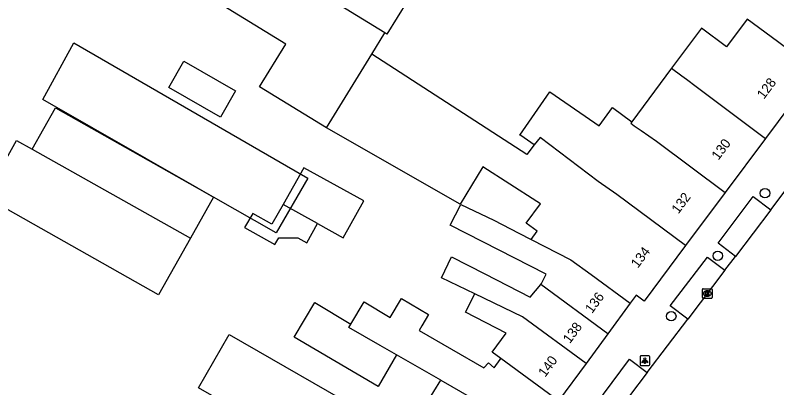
# Model space of a CAD drawing. Extents: x 160107 to 160928, y 382056 to 382918.
# Drawn here: x 160581.9 to 160660.5, y 382406.2 to 382444.7 of the extents above; entities that cross this region are included whole.
import ezdxf

# ---------------------------------------------------------------- set-up
doc = ezdxf.new("R2010")
doc.units = 0
for name, color, linetype in [('IMGEO_Boom', 7, 'Continuous'), ('IMGEO_Kolk', 7, 'Continuous'), ('IMGEO_Lichtpunt', 7, 'Continuous'), ('IMGEO_Pand', 7, 'Continuous'), ('IMGEO_Pand_nummerreeks', 7, 'Continuous'), ('IMGEO_Pand_vergunning_verleend', 7, 'Continuous'), ('IMGEO_Rijbaan_lokaal_gesloten', 7, 'Continuous'), ('IMGEO_Rijbaan_lokaal_open', 7, 'Continuous'), ('IMGEO_Voetpad_open', 7, 'Continuous')]:
    doc.layers.add(name, color=color, linetype=linetype)

msp = doc.modelspace()

# ---------------------------------------------------------------- linework, layer by layer
at = {"layer": 'IMGEO_Boom'}
for centre in [(160659.237, 382426.272), (160654.363, 382419.812), (160649.565, 382413.572)]:
    msp.add_circle(centre, 0.489, dxfattribs=at)
at = {"layer": 'IMGEO_Kolk'}
for p, q in [((160652.778, 382415.488), (160652.778, 382416.34)), ((160652.853, 382416.414), (160653.705, 382416.414)), ((160653.779, 382416.34), (160653.779, 382415.488)), ((160653.289, 382415.634), (160653.264, 382415.634)), ((160653.266, 382416.194), (160653.291, 382416.194)), ((160653.705, 382415.414), (160652.853, 382415.414))]:
    msp.add_line(p, q, dxfattribs=at)
for points in [[(160652.778, 382415.488), (160652.778, 382416.34)], [(160652.853, 382416.414), (160653.705, 382416.414)], [(160653.779, 382416.34), (160653.779, 382415.488)], [(160653.099, 382416.114), (160653.222, 382416.114), (160653.222, 382415.963), (160653.352, 382416.114), (160653.516, 382416.114), (160653.37, 382415.963), (160653.523, 382415.714), (160653.371, 382415.714), (160653.286, 382415.878), (160653.222, 382415.811), (160653.222, 382415.714), (160653.099, 382415.714), (160653.099, 382416.114)], [(160653.705, 382415.414), (160652.853, 382415.414)]]:
    msp.add_lwpolyline(points, dxfattribs=at)
for centre, start, end in [((160652.855, 382416.338), 91.55205, 178.44795), ((160652.855, 382416.338), 91.55205, 178.44795), ((160653.703, 382416.338), 1.55205, 88.44795), ((160653.703, 382416.338), 1.55205, 88.44795), ((160652.855, 382415.49), 181.55205, 268.44795), ((160652.855, 382415.49), 181.55205, 268.44795), ((160653.703, 382415.49), 271.55205, 358.44795), ((160653.703, 382415.49), 271.55205, 358.44795)]:
    msp.add_arc(centre, 0.0765, start, end, dxfattribs=at)
for centre, major_axis, ratio, start_param, end_param in [((160653.265, 382415.914), (-0.387, 0.002), 0.722429, 4.712389, 7.853982), ((160653.29, 382415.914), (-0.39, 0.002), 0.717154, 1.570796, 4.712389)]:
    msp.add_ellipse(centre, major_axis=major_axis, ratio=ratio, start_param=start_param, end_param=end_param, dxfattribs=at)
at = {"layer": 'IMGEO_Lichtpunt'}
for p, q in [((160646.344, 382409.379), (160646.344, 382408.572)), ((160646.344, 382409.379), (160646.344, 382408.572)), ((160647.246, 382409.474), (160646.438, 382409.474)), ((160647.246, 382409.474), (160646.438, 382409.474)), ((160647.34, 382408.572), (160647.34, 382409.379)), ((160647.34, 382408.572), (160647.34, 382409.379)), ((160646.438, 382408.478), (160647.246, 382408.478)), ((160646.438, 382408.478), (160647.246, 382408.478))]:
    msp.add_line(p, q, dxfattribs=at)
for points in [[(160646.718, 382409.043), (160646.757, 382409.015), (160646.569, 382408.753), (160646.531, 382408.78), (160646.718, 382409.043)], [(160646.82, 382408.995), (160646.867, 382408.995), (160646.867, 382408.673), (160646.82, 382408.673), (160646.82, 382408.995)], [(160646.93, 382409.015), (160646.968, 382409.042), (160647.155, 382408.78), (160647.116, 382408.752), (160646.93, 382409.015)]]:
    msp.add_lwpolyline(points, dxfattribs=at)
msp.add_circle((160646.843, 382409.177), 0.0994, dxfattribs=at)
for centre, start, end in [((160646.438, 382409.379), 90, 180), ((160646.438, 382409.379), 90, 180), ((160647.246, 382409.379), 0, 90), ((160647.246, 382409.379), 0, 90), ((160646.438, 382408.572), 180, 270), ((160646.438, 382408.572), 180, 270), ((160647.246, 382408.572), 270, 0), ((160647.246, 382408.572), 270, 360)]:
    msp.add_arc(centre, 0.0946, start, end, dxfattribs=at)
at = {"layer": 'IMGEO_Pand'}
for points in [[(160620.004, 382442.836), (160575.406, 382470.174)], [(160613.991, 382433.026), (160607.091, 382437.255), (160609.795, 382441.666), (160575.28, 382462.823)], [(160664.522, 382438.938), (160660.514, 382441.927), (160657.392, 382444.254), (160655.259, 382441.394), (160652.682, 382443.316), (160649.596, 382439.179)], [(160618.664, 382440.649), (160620.004, 382442.836)], [(160597.704, 382437.19), (160599.252, 382439.907), (160604.599, 382436.862), (160603.051, 382434.144), (160597.704, 382437.19)], [(160613.991, 382433.026), (160618.664, 382440.649)], [(160635.434, 382431.256), (160634.673, 382430.285), (160618.664, 382440.649)], [(160649.596, 382439.179), (160645.482, 382433.635)], [(160649.596, 382439.179), (160650.667, 382438.38), (160651.128, 382438.036), (160652.134, 382437.286), (160659.305, 382431.941)], [(160664.522, 382438.938), (160659.305, 382431.941)], [(160635.434, 382431.256), (160634.036, 382432.219), (160633.953, 382432.277), (160637.034, 382436.749), (160641.689, 382433.542), (160642.114, 382433.249), (160643.494, 382435.11), (160645.482, 382433.635)], [(160645.482, 382433.635), (160645.377, 382433.493), (160645.723, 382433.249), (160646.461, 382432.738), (160648.035, 382431.648), (160655.137, 382426.352)], [(160635.11, 382421.495), (160635.734, 382422.345), (160634.6, 382423.179), (160636.066, 382425.184), (160635.704, 382425.415), (160630.126, 382428.982), (160627.774, 382425.149), (160613.991, 382433.026)], [(160651.041, 382420.859), (160643.936, 382426.153), (160642.037, 382427.497), (160636.044, 382432.035), (160635.434, 382431.256)], [(160659.305, 382431.941), (160655.137, 382426.352)], [(160613.063, 382423.138), (160615.698, 382421.665), (160617.851, 382425.482), (160611.657, 382428.902), (160609.522, 382425.119)], [(160655.137, 382426.352), (160651.041, 382420.859)], [(160609.522, 382425.119), (160608.366, 382423.07), (160606.374, 382424.193), (160605.543, 382422.721), (160608.662, 382420.961), (160609.057, 382421.662), (160611.035, 382421.658), (160611.95, 382421.142), (160613.063, 382423.138)], [(160613.063, 382423.138), (160609.522, 382425.119)], [(160636.09, 382416.849), (160636.175, 382416.953), (160636.661, 382417.906), (160630.119, 382421.246), (160626.753, 382422.964), (160627.85, 382425.113), (160631.259, 382423.479), (160633.849, 382422.156), (160635.11, 382421.495)], [(160635.11, 382421.495), (160639.203, 382419.406), (160641.302, 382417.865), (160645.332, 382414.905)], [(160651.041, 382420.859), (160646.772, 382415.134), (160645.95, 382415.747), (160645.332, 382414.905)], [(160629.287, 382415.879), (160625.863, 382417.531), (160626.904, 382419.69), (160630.338, 382417.936), (160635.017, 382415.547), (160636.09, 382416.849)], [(160643.022, 382411.759), (160636.09, 382416.849)], [(160631.971, 382409.192), (160631.07, 382409.853), (160632.525, 382411.833), (160628.318, 382413.981), (160629.287, 382415.879)], [(160640.769, 382408.693), (160634.23, 382413.494), (160629.287, 382415.879)], [(160621.207, 382409.593), (160619.305, 382406.32), (160610.656, 382411.413), (160612.774, 382415.002), (160616.496, 382412.737)], [(160616.496, 382412.737), (160617.872, 382415.052), (160620.566, 382413.451), (160621.718, 382415.403), (160624.511, 382413.766), (160623.822, 382412.569), (160623.547, 382412.092), (160630.222, 382408.252), (160630.691, 382408.771), (160631.274, 382408.244), (160631.901, 382409.097), (160631.971, 382409.192)], [(160645.332, 382414.905), (160643.022, 382411.759)], [(160621.207, 382409.593), (160619.523, 382410.562), (160616.302, 382412.411), (160616.496, 382412.737)], [(160603.933, 382411.678), (160618.421, 382403.365), (160615.257, 382397.851), (160614.438, 382398.321), (160600.769, 382406.163), (160603.933, 382411.678)], [(160643.022, 382411.759), (160640.769, 382408.693)], [(160625.785, 382406.959), (160621.207, 382409.593)], [(160637.926, 382404.821), (160631.971, 382409.192)], [(160640.769, 382408.693), (160637.926, 382404.821)], [(160624.966, 382399.89), (160626.373, 382401.805), (160625.763, 382402.294), (160623.729, 382403.674), (160624.326, 382404.628), (160625.785, 382406.959)], [(160625.785, 382406.959), (160636.404, 382400.85)]]:
    msp.add_lwpolyline(points, dxfattribs=at)
at = {"layer": 'IMGEO_Pand_vergunning_verleend'}
for points in [[(160600.638, 382426.845), (160584.72, 382435.955), (160587.904, 382441.788), (160612.058, 382427.84), (160608.811, 382422.167), (160602.337, 382425.872)], [(160583.61, 382430.833), (160586.013, 382435.102), (160600.638, 382426.845)], [(160599.953, 382421.634), (160596.667, 382415.795), (160578.727, 382425.893), (160582.013, 382431.732), (160583.61, 382430.833)], [(160583.61, 382430.833), (160599.953, 382421.634)], [(160602.337, 382425.872), (160600.638, 382426.845)], [(160600.638, 382426.845), (160602.343, 382425.882), (160602.337, 382425.872)], [(160602.337, 382425.872), (160599.953, 382421.634)]]:
    msp.add_lwpolyline(points, dxfattribs=at)
at = {"layer": 'IMGEO_Rijbaan_lokaal_gesloten'}
for points in [[(160659.831, 382424.555), (160663.086, 382428.847)], [(160659.831, 382424.555), (160656.184, 382419.745)], [(160655.099, 382418.315), (160656.184, 382419.745)], [(160655.099, 382418.315), (160651.261, 382413.256)], [(160647.085, 382407.756), (160651.261, 382413.256)], [(160647.085, 382407.756), (160643.431, 382402.943)]]:
    msp.add_lwpolyline(points, dxfattribs=at)
at = {"layer": 'IMGEO_Rijbaan_lokaal_open'}
msp.add_lwpolyline([(160623.399, 382447.911), (160620.206, 382442.715), (160620.004, 382442.836)], dxfattribs=at)
at = {"layer": 'IMGEO_Voetpad_open'}
for points in [[(160656.184, 382419.745), (160654.388, 382421.113), (160658.012, 382425.924), (160659.831, 382424.555)], [(160651.261, 382413.256), (160649.459, 382414.646), (160653.32, 382419.673), (160655.099, 382418.315)], [(160643.431, 382402.943), (160641.662, 382404.316), (160645.261, 382409.125), (160647.085, 382407.756)]]:
    msp.add_lwpolyline(points, dxfattribs=at)

# ---------------------------------------------------------------- texts
at = {"layer": 'IMGEO_Pand_nummerreeks'}
for s, rotation, p in [('128', 53.2908, (160659.125, 382435.917)), ('130', 53.2908, (160654.433, 382429.624)), ('132', 53.2908, (160650.298, 382424.078)), ('134', 53.2908, (160646.117, 382418.47)), ('136', 53.70333, (160641.385, 382413.786)), ('138', 53.70333, (160639.105, 382410.683)), ('140', 53.70333, (160636.557, 382407.213))]:
    msp.add_text(s, height=1, rotation=rotation, dxfattribs=at).set_placement(p)

doc.saveas('drawing.dxf')
